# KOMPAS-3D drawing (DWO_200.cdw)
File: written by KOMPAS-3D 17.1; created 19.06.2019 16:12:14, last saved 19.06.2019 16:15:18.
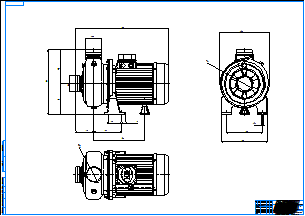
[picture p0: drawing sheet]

Sheet 1: A0, landscape

Title block, sheet 1: name: DWO_200; material: Внимание! Данный продукт является объектом авторского права ООО «Торговый Дом АДЛ». / Запрещается изменение, копирование, распространение / (в том числе путем копирования на другие сайты и ресурсы в Интернете) / или любое иное использование информации и объектов без предварительного / согласия правообладателя (ООО «Торговый Дом АДЛ»).; scale: 1:1; sheets: 1; organisation: ООО "Торговый дом АДЛ"; sheet format: A0; stored path: \\adlc.lan\data\АДЛ_ПКД\3D-модели\Поставщики\Насосное оборудование EBARA\DWO\KOMPAS 2D\DWO_200.cdw

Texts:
  user
  CONTINUOUS_RGB_0_0_0_THICK_0.18
  POLYLINE_STYLE_0.18_RGB_0_0_0
Dimensions and other numbers on the sheet: 107; 364; 198.5; 74; 50; 15; 120; 133; 253; 62.5; 193; 140; 180; 9; 57; 1:1; 1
